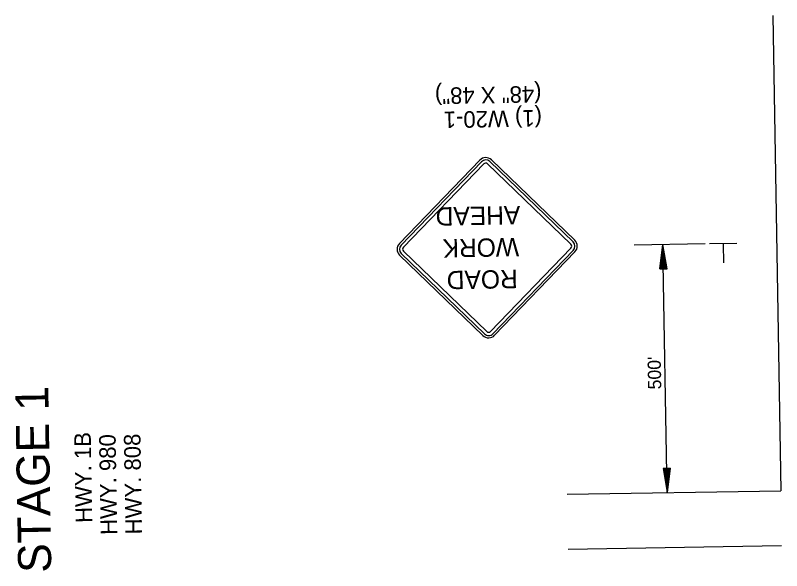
# Model space of a CAD drawing. Extents: x 1676063 to 1678026, y 228339 to 229904.
# Drawn here: x 1677328.4 to 1677606.4, y 229093.9 to 229295.5 of the extents above; entities that cross this region are included whole.
import ezdxf

# ---------------------------------------------------------------- set-up
doc = ezdxf.new("R2010")
doc.units = 0
for name, color, linetype in [('P_TC_Signs_Temporary', 7, 'Continuous'), ('R_Annotation', 7, 'Continuous'), ('R_Draft', 7, 'Continuous')]:
    doc.layers.add(name, color=color, linetype=linetype)

msp = doc.modelspace()

# ---------------------------------------------------------------- linework, layer by layer
at = {"layer": 'P_TC_Signs_Temporary'}
for p, q in [((1677467.73, 229212.66), (1677496.88, 229242.89)), ((1677501.12, 229242.97), (1677531.35, 229213.82)), ((1677468.33, 229212.08), (1677497.48, 229242.32)), ((1677469.17, 229211.27), (1677498.32, 229241.51)), ((1677499.73, 229241.53), (1677529.97, 229212.38)), ((1677500.54, 229242.37), (1677530.78, 229213.22)), ((1677499.43, 229180.7), (1677469.19, 229209.86)), ((1677529.99, 229210.96), (1677500.84, 229180.73)), ((1677530.83, 229210.16), (1677501.68, 229179.92)), ((1677531.43, 229209.58), (1677502.28, 229179.34)), ((1677498.04, 229179.26), (1677467.8, 229208.42)), ((1677498.62, 229179.86), (1677468.38, 229209.02))]:
    msp.add_line(p, q, dxfattribs=at)
for centre, radius, start, end in [((1677499.04, 229240.81), 3, 46.0434, 136.0434), ((1677499.04, 229240.81), 2.17, 46.0434, 136.0434), ((1677499.04, 229240.81), 1, 46.0434, 136.0434), ((1677469.89, 229210.58), 3, 136.0434, 226.0434), ((1677529.27, 229211.66), 1, 316.0434, 46.0434), ((1677529.27, 229211.66), 2.17, 316.0434, 46.0434), ((1677529.27, 229211.66), 3, 316.0434, 46.0434), ((1677469.89, 229210.58), 2.17, 136.0434, 226.0434), ((1677469.89, 229210.58), 1, 136.0434, 226.0434), ((1677500.12, 229181.42), 3, 226.0434, 316.0434), ((1677500.12, 229181.42), 2.17, 226.0434, 316.0434), ((1677500.12, 229181.42), 1, 226.0434, 316.0434)]:
    msp.add_arc(centre, radius, start, end, dxfattribs=at)
at = {"layer": 'R_Draft'}
for p, q in [((1677603.24, 229295.45), (1677606.1, 229122.94)), ((1677578.67, 229212.48), (1677552.92, 229212.06)), ((1677590.18, 229212.67), (1677580.28, 229212.5)), ((1677585.25, 229212.44), (1677585.36, 229205.69)), ((1677562.19, 229203.41), (1677563.37, 229212.23)), ((1677562.41, 229203.41), (1677563.39, 229210.76)), ((1677564.86, 229122.26), (1677563.37, 229212.23)), ((1677564.83, 229203.45), (1677563.37, 229212.23)), ((1677564.61, 229203.45), (1677563.39, 229210.76)), ((1677562.64, 229203.41), (1677563.42, 229209.25)), ((1677562.86, 229203.42), (1677563.44, 229207.78)), ((1677564.39, 229203.44), (1677563.42, 229209.25)), ((1677564.17, 229203.44), (1677563.44, 229207.78)), ((1677563.09, 229203.42), (1677563.47, 229206.29)), ((1677563.31, 229203.43), (1677563.49, 229204.82)), ((1677563.94, 229203.44), (1677563.47, 229206.29)), ((1677563.72, 229203.43), (1677563.49, 229204.82)), ((1677562.19, 229203.41), (1677564.83, 229203.45)), ((1677566.03, 229131.08), (1677563.39, 229131.04)), ((1677563.39, 229131.04), (1677564.86, 229122.26)), ((1677563.61, 229131.04), (1677564.83, 229123.73)), ((1677563.84, 229131.05), (1677564.81, 229125.24)), ((1677564.06, 229131.05), (1677564.78, 229126.71)), ((1677564.28, 229131.05), (1677564.76, 229128.2)), ((1677564.51, 229131.06), (1677564.74, 229129.67)), ((1677564.92, 229131.06), (1677564.74, 229129.67)), ((1677565.14, 229131.07), (1677564.76, 229128.2)), ((1677565.37, 229131.07), (1677564.78, 229126.71)), ((1677565.59, 229131.07), (1677564.81, 229125.24)), ((1677565.81, 229131.08), (1677564.83, 229123.73)), ((1677566.03, 229131.08), (1677564.86, 229122.26)), ((1677528.66, 229121.66), (1677606.1, 229122.94)), ((1677528.99, 229101.71), (1677606.43, 229103))]:
    msp.add_line(p, q, dxfattribs=at)

# ---------------------------------------------------------------- texts
at = {"layer": 'P_TC_Signs_Temporary'}
for s, p in [(' AHEAD ', (1677514.01, 229226.35)), ('WORK', (1677511.06, 229214.71)), (' ROAD ', (1677513.08, 229203.17))]:
    msp.add_text(s, height=6.667, rotation=181.0434, dxfattribs=at).set_placement(p)
at = {"layer": 'R_Annotation'}
for s, height, rotation, p in [('(48" X 48")', 6, 181.0434, (1677519.25, 229269.88)), ('(1) W20-1', 6, 181.0434, (1677519.41, 229261.15)), ("500'", 4.8, 90.9497, (1677562.75, 229159.72)), ('STAGE 1', 12, 90.9497, (1677341.44, 229093.23)), ('HWY. 1B', 6, 90.9497, (1677356.28, 229111.28)), ('HWY. 980', 6, 90.9497, (1677365.35, 229106.94)), ('HWY. 808', 6, 90.9497, (1677374.35, 229107.12))]:
    msp.add_text(s, height=height, rotation=rotation, dxfattribs=at).set_placement(p)

doc.saveas('drawing.dxf')
